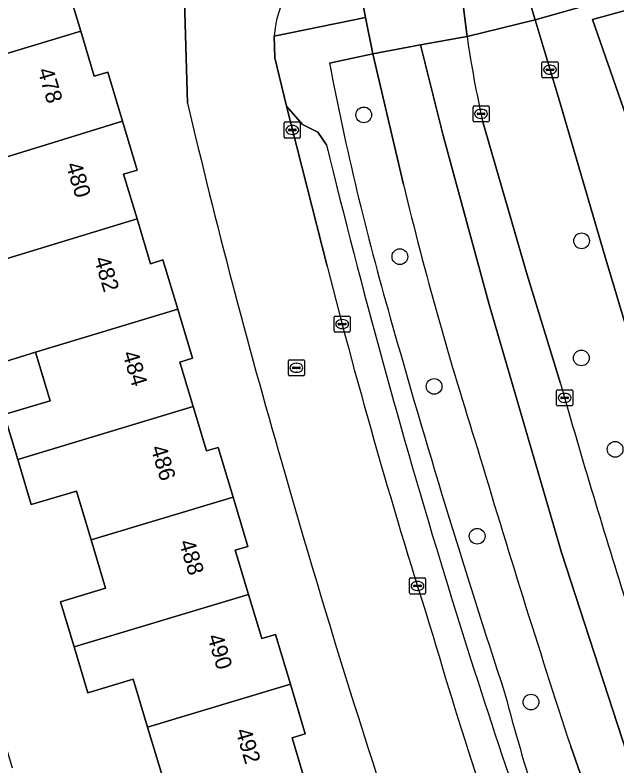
# Model space of a CAD drawing. Extents: x 157767 to 159172, y 387839 to 389425.
# Drawn here: x 158451.48 to 158488.94, y 388405.41 to 388452.12 of the extents above; entities that cross this region are included whole.
import ezdxf

# ---------------------------------------------------------------- set-up
doc = ezdxf.new("R2010")
doc.units = 0
for name, color, linetype in [('IMGEO_Berm_groen', 7, 'Continuous'), ('IMGEO_Boom', 7, 'Continuous'), ('IMGEO_Erf', 7, 'Continuous'), ('IMGEO_Kolk', 7, 'Continuous'), ('IMGEO_Pand', 7, 'Continuous'), ('IMGEO_Pand_nummerreeks', 7, 'Continuous'), ('IMGEO_Parkeervlak_open', 7, 'Continuous'), ('IMGEO_Rijbaan_lokaal_gesloten', 7, 'Continuous'), ('IMGEO_Rijbaan_lokaal_open', 7, 'Continuous'), ('IMGEO_Rioolput', 7, 'Continuous'), ('IMGEO_Verkeerseiland_open', 7, 'Continuous'), ('IMGEO_Voetpad_open', 7, 'Continuous')]:
    doc.layers.add(name, color=color, linetype=linetype)

msp = doc.modelspace()

# ---------------------------------------------------------------- linework, layer by layer
at = {"layer": 'IMGEO_Berm_groen'}
for points in [[(158490.865, 388428.213), (158488.179, 388437.145), (158485.337, 388446.848), (158483.846, 388451.832), (158479.618, 388450.796)], [(158475.648, 388441.591), (158473.746, 388449.709), (158471.053, 388449.136)], [(158480.585, 388445.534), (158483.359, 388435.96), (158485.431, 388429.209)], [(158486.242, 388396.474), (158490.11, 388386.526), (158492.771, 388387.635), (158492.15, 388389.247), (158486.063, 388406.631)]]:
    msp.add_lwpolyline(points, dxfattribs=at)
for centre, radius, start, end in [((158541.405, 388459.431), 62.388, 187.95561, 192.87057), ((158644.262, 388482.145), 176.326, 190.7896, 196.08308), ((158711.3, 388498.942), 242.53, 193.67831, 197.70967), ((159003.836, 388581.934), 549.484, 195.69418, 198.24389), ((158948.437, 388560.582), 481.283, 195.84072, 197.57658), ((159143.333, 388622.48), 691.805, 196.571755, 198.180292), ((158614.02, 388444.466), 136.494, 194.66486, 200.58574)]:
    msp.add_arc(centre, radius, start, end, dxfattribs=at)
at = {"layer": 'IMGEO_Boom'}
for centre in [(158473.184, 388445.913), (158486.742, 388438.079), (158475.434, 388437.093), (158486.726, 388430.793), (158477.565, 388429.023), (158488.828, 388425.109), (158480.242, 388419.704), (158483.595, 388409.388)]:
    msp.add_circle(centre, 0.489, dxfattribs=at)
at = {"layer": 'IMGEO_Erf'}
for points in [[(158462.219, 388446.634), (158461.817, 388460.067), (158461.803, 388460.531), (158434.092, 388452.282), (158434.544, 388450.562), (158437.436, 388451.432), (158439.023, 388446.154), (158440.77, 388440.344), (158442.52, 388434.523), (158444.276, 388428.684), (158446.04, 388422.816), (158447.8, 388416.963), (158449.546, 388411.158), (158451.307, 388405.301)], [(158454.733, 388453.91), (158455.574, 388451.115), (158456.414, 388448.321), (158457.247, 388448.571), (158458.163, 388445.526), (158459.079, 388442.478), (158458.238, 388442.225), (158459.075, 388439.443), (158459.912, 388436.658), (158460.683, 388436.89), (158461.604, 388433.826), (158462.521, 388430.777), (158461.73, 388430.539), (158462.562, 388427.772), (158463.392, 388425.011), (158464.123, 388425.23), (158465.051, 388422.144), (158465.976, 388419.066), (158465.184, 388418.828), (158466.01, 388416.082), (158466.835, 388413.338), (158467.686, 388413.593), (158468.616, 388410.499), (158469.547, 388407.404), (158468.726, 388407.157), (158469.562, 388404.375)], [(158460.631, 388404.824), (158459.726, 388407.834), (158458.832, 388410.807), (158456.011, 388409.959), (158455.152, 388412.818), (158454.306, 388415.631), (158457.114, 388416.476), (158456.211, 388419.477), (158455.298, 388422.514), (158452.493, 388421.671), (158451.652, 388424.467), (158450.808, 388427.275), (158453.668, 388428.135), (158452.763, 388431.146), (158449.935, 388430.289)]]:
    msp.add_lwpolyline(points, dxfattribs=at)
for centre, radius, start, end in [((158897.479, 388548.97), 447.128, 193.23077, 196.1824), ((158987.407, 388571.626), 539.818, 195.83174, 199.15454)]:
    msp.add_arc(centre, radius, start, end, dxfattribs=at)
at = {"layer": 'IMGEO_Kolk'}
for p, q in [((158484.275, 388448.296), (158484.275, 388449.148)), ((158484.35, 388449.222), (158485.202, 388449.222)), ((158484.763, 388449.002), (158484.788, 388449.002)), ((158485.276, 388449.148), (158485.276, 388448.296)), ((158484.534, 388448.716), (158484.534, 388448.728)), ((158484.972, 388448.679), (158484.574, 388448.679)), ((158484.577, 388448.765), (158484.975, 388448.765)), ((158484.786, 388448.442), (158484.761, 388448.442)), ((158485.018, 388448.728), (158485.018, 388448.716)), ((158485.202, 388448.222), (158484.35, 388448.222)), ((158479.985, 388445.551), (158479.985, 388446.403)), ((158480.06, 388446.477), (158480.912, 388446.477)), ((158480.473, 388446.257), (158480.498, 388446.257)), ((158480.986, 388446.403), (158480.986, 388445.551)), ((158480.244, 388445.971), (158480.244, 388445.983)), ((158480.682, 388445.934), (158480.284, 388445.934)), ((158480.287, 388446.02), (158480.685, 388446.02)), ((158480.496, 388445.697), (158480.471, 388445.697)), ((158480.728, 388445.983), (158480.728, 388445.971)), ((158468.236, 388444.547), (158468.236, 388445.399)), ((158468.311, 388445.473), (158469.163, 388445.473)), ((158468.724, 388445.253), (158468.749, 388445.253)), ((158469.237, 388445.399), (158469.237, 388444.547)), ((158480.912, 388445.477), (158480.06, 388445.477)), ((158468.495, 388444.967), (158468.495, 388444.979)), ((158468.933, 388444.93), (158468.535, 388444.93)), ((158468.538, 388445.016), (158468.936, 388445.016)), ((158468.747, 388444.693), (158468.722, 388444.693)), ((158468.979, 388444.979), (158468.979, 388444.967)), ((158469.163, 388444.473), (158468.311, 388444.473)), ((158471.338, 388432.474), (158471.338, 388433.326)), ((158471.413, 388433.4), (158472.265, 388433.4)), ((158471.826, 388433.18), (158471.851, 388433.18)), ((158472.339, 388433.326), (158472.339, 388432.474)), ((158471.597, 388432.894), (158471.597, 388432.906)), ((158472.035, 388432.857), (158471.637, 388432.857)), ((158471.64, 388432.943), (158472.038, 388432.943)), ((158471.849, 388432.62), (158471.824, 388432.62)), ((158472.081, 388432.906), (158472.081, 388432.894)), ((158472.265, 388432.4), (158471.413, 388432.4)), ((158485.261, 388428.812), (158486.113, 388428.812)), ((158485.186, 388427.886), (158485.186, 388428.738)), ((158485.445, 388428.306), (158485.445, 388428.318)), ((158485.488, 388428.355), (158485.886, 388428.355)), ((158485.674, 388428.592), (158485.699, 388428.592)), ((158485.929, 388428.318), (158485.929, 388428.306)), ((158486.187, 388428.738), (158486.187, 388427.886)), ((158485.883, 388428.269), (158485.485, 388428.269)), ((158485.697, 388428.032), (158485.672, 388428.032)), ((158486.113, 388427.812), (158485.261, 388427.812)), ((158476.101, 388417.11), (158476.953, 388417.11)), ((158476.026, 388416.184), (158476.026, 388417.036)), ((158476.328, 388416.653), (158476.726, 388416.653)), ((158476.514, 388416.89), (158476.539, 388416.89)), ((158477.027, 388417.036), (158477.027, 388416.184)), ((158476.285, 388416.604), (158476.285, 388416.616)), ((158476.723, 388416.567), (158476.325, 388416.567)), ((158476.537, 388416.33), (158476.512, 388416.33)), ((158476.769, 388416.616), (158476.769, 388416.604)), ((158476.953, 388416.11), (158476.101, 388416.11))]:
    msp.add_line(p, q, dxfattribs=at)
for points in [[(158484.275, 388448.296), (158484.275, 388449.148)], [(158484.35, 388449.222), (158485.202, 388449.222)], [(158485.276, 388449.148), (158485.276, 388448.296)], [(158485.202, 388448.222), (158484.35, 388448.222)], [(158479.985, 388445.551), (158479.985, 388446.403)], [(158480.06, 388446.477), (158480.912, 388446.477)], [(158480.986, 388446.403), (158480.986, 388445.551)], [(158468.236, 388444.547), (158468.236, 388445.399)], [(158468.311, 388445.473), (158469.163, 388445.473)], [(158469.237, 388445.399), (158469.237, 388444.547)], [(158480.912, 388445.477), (158480.06, 388445.477)], [(158469.163, 388444.473), (158468.311, 388444.473)], [(158471.338, 388432.474), (158471.338, 388433.326)], [(158471.413, 388433.4), (158472.265, 388433.4)], [(158472.339, 388433.326), (158472.339, 388432.474)], [(158472.265, 388432.4), (158471.413, 388432.4)], [(158485.261, 388428.812), (158486.113, 388428.812)], [(158485.186, 388427.886), (158485.186, 388428.738)], [(158486.187, 388428.738), (158486.187, 388427.886)], [(158486.113, 388427.812), (158485.261, 388427.812)], [(158476.101, 388417.11), (158476.953, 388417.11)], [(158476.026, 388416.184), (158476.026, 388417.036)], [(158477.027, 388417.036), (158477.027, 388416.184)], [(158476.953, 388416.11), (158476.101, 388416.11)]]:
    msp.add_lwpolyline(points, dxfattribs=at)
for centre, radius, start, end in [((158484.352, 388449.146), 0.0765, 91.552, 178.448), ((158484.352, 388449.146), 0.0765, 91.552, 178.448), ((158485.2, 388449.146), 0.0765, 1.552, 88.448), ((158485.2, 388449.146), 0.0765, 1.552, 88.448), ((158484.574, 388448.725), 0.0403, 85.8775, 175.7526), ((158484.571, 388448.715), 0.0366, 178.938, 274.7102), ((158484.975, 388448.722), 0.043, 264.8664, 352.4533), ((158484.979, 388448.727), 0.0386, 1.7309, 96.639), ((158484.352, 388448.298), 0.0765, 181.552, 268.448), ((158484.352, 388448.298), 0.0765, 181.552, 268.448), ((158485.2, 388448.298), 0.0765, 271.552, 358.448), ((158485.2, 388448.298), 0.0765, 271.552, 358.448), ((158480.062, 388446.401), 0.0765, 91.552, 178.448), ((158480.062, 388446.401), 0.0765, 91.552, 178.448), ((158480.91, 388446.401), 0.0765, 1.552, 88.448), ((158480.91, 388446.401), 0.0765, 1.552, 88.448), ((158480.284, 388445.98), 0.0403, 85.8775, 175.7526), ((158480.281, 388445.97), 0.0366, 178.938, 274.7102), ((158480.685, 388445.977), 0.043, 264.8664, 352.4533), ((158480.689, 388445.982), 0.0386, 1.7309, 96.639), ((158468.313, 388445.397), 0.0765, 91.552, 178.448), ((158468.313, 388445.397), 0.0765, 91.552, 178.448), ((158469.161, 388445.397), 0.0765, 1.552, 88.448), ((158469.161, 388445.397), 0.0765, 1.552, 88.448), ((158480.062, 388445.553), 0.0765, 181.552, 268.448), ((158480.062, 388445.553), 0.0765, 181.552, 268.448), ((158480.91, 388445.553), 0.0765, 271.552, 358.448), ((158480.91, 388445.553), 0.0765, 271.552, 358.448), ((158468.535, 388444.976), 0.0403, 85.8775, 175.7526), ((158468.532, 388444.966), 0.0366, 178.938, 274.7102), ((158468.936, 388444.973), 0.043, 264.8664, 352.4533), ((158468.94, 388444.978), 0.0386, 1.7309, 96.639), ((158468.313, 388444.549), 0.0765, 181.552, 268.448), ((158468.313, 388444.549), 0.0765, 181.552, 268.448), ((158469.161, 388444.549), 0.0765, 271.552, 358.448), ((158469.161, 388444.549), 0.0765, 271.552, 358.448), ((158471.415, 388433.324), 0.0765, 91.552, 178.448), ((158471.415, 388433.324), 0.0765, 91.552, 178.448), ((158472.263, 388433.324), 0.0765, 1.552, 88.448), ((158472.263, 388433.324), 0.0765, 1.552, 88.448), ((158471.637, 388432.903), 0.0403, 85.8775, 175.7526), ((158471.634, 388432.893), 0.0366, 178.938, 274.7102), ((158472.038, 388432.9), 0.043, 264.8664, 352.4533), ((158472.042, 388432.905), 0.0386, 1.7309, 96.639), ((158471.415, 388432.476), 0.0765, 181.552, 268.448), ((158471.415, 388432.476), 0.0765, 181.552, 268.448), ((158472.263, 388432.476), 0.0765, 271.552, 358.448), ((158472.263, 388432.476), 0.0765, 271.552, 358.448), ((158485.263, 388428.736), 0.0765, 91.552, 178.448), ((158485.263, 388428.736), 0.0765, 91.552, 178.448), ((158486.111, 388428.736), 0.0765, 1.552, 88.448), ((158486.111, 388428.736), 0.0765, 1.552, 88.448), ((158485.485, 388428.315), 0.0403, 85.8775, 175.7526), ((158485.482, 388428.305), 0.0366, 178.938, 274.7102), ((158485.886, 388428.312), 0.043, 264.8664, 352.4533), ((158485.89, 388428.317), 0.0386, 1.7309, 96.639), ((158485.263, 388427.888), 0.0765, 181.552, 268.448), ((158485.263, 388427.888), 0.0765, 181.552, 268.448), ((158486.111, 388427.888), 0.0765, 271.552, 358.448), ((158486.111, 388427.888), 0.0765, 271.552, 358.448), ((158476.103, 388417.034), 0.0765, 91.552, 178.448), ((158476.103, 388417.034), 0.0765, 91.552, 178.448), ((158476.951, 388417.034), 0.0765, 1.552, 88.448), ((158476.951, 388417.034), 0.0765, 1.552, 88.448), ((158476.325, 388416.613), 0.0403, 85.8775, 175.7526), ((158476.73, 388416.615), 0.0386, 1.7309, 96.639), ((158476.103, 388416.186), 0.0765, 181.552, 268.448), ((158476.103, 388416.186), 0.0765, 181.552, 268.448), ((158476.322, 388416.603), 0.0366, 178.938, 274.7102), ((158476.726, 388416.61), 0.043, 264.8664, 352.4533), ((158476.951, 388416.186), 0.0765, 271.552, 358.448), ((158476.951, 388416.186), 0.0765, 271.552, 358.448)]:
    msp.add_arc(centre, radius, start, end, dxfattribs=at)
for centre, major_axis, ratio, start_param, end_param in [((158484.762, 388448.722), (-0.387, 0.002), 0.722429, 4.712389, 7.853982), ((158484.787, 388448.722), (-0.39, 0.002), 0.717154, 1.570796, 4.712389), ((158480.472, 388445.977), (-0.387, 0.002), 0.722429, 4.712389, 7.853982), ((158480.497, 388445.977), (-0.39, 0.002), 0.717154, 1.570796, 4.712389), ((158468.723, 388444.973), (-0.387, 0.002), 0.722429, 4.712389, 7.853982), ((158468.748, 388444.973), (-0.39, 0.002), 0.717154, 1.570796, 4.712389), ((158471.825, 388432.9), (-0.387, 0.002), 0.722429, 4.712389, 7.853982), ((158471.85, 388432.9), (-0.39, 0.002), 0.717154, 1.570796, 4.712389), ((158485.673, 388428.312), (-0.387, 0.002), 0.722429, 4.712389, 7.853982), ((158485.698, 388428.312), (-0.39, 0.002), 0.717154, 1.570796, 4.712389), ((158476.513, 388416.61), (-0.387, 0.002), 0.722429, 4.712389, 7.853982), ((158476.538, 388416.61), (-0.39, 0.002), 0.717154, 1.570796, 4.712389)]:
    msp.add_ellipse(centre, major_axis=major_axis, ratio=ratio, start_param=start_param, end_param=end_param, dxfattribs=at)
at = {"layer": 'IMGEO_Pand'}
for points in [[(158444.709, 388447.842), (158455.574, 388451.115), (158454.733, 388453.91), (158455.527, 388454.149), (158454.564, 388457.354), (158445.669, 388454.68), (158446.645, 388451.436), (158443.878, 388450.604)], [(158458.163, 388445.526), (158457.247, 388448.571), (158456.414, 388448.321), (158455.574, 388451.115), (158444.709, 388447.842), (158445.318, 388445.816), (158445.538, 388445.084), (158448.408, 388445.946), (158449.349, 388442.815)], [(158448.182, 388436.123), (158459.075, 388439.443), (158458.238, 388442.225), (158459.079, 388442.478), (158458.163, 388445.526), (158449.349, 388442.815), (158450.252, 388439.812), (158447.336, 388438.936)], [(158460.683, 388436.89), (158459.912, 388436.658), (158459.075, 388439.443), (158448.182, 388436.123), (158449.009, 388433.371), (158449.935, 388430.289), (158452.763, 388431.146), (158461.604, 388433.826)], [(158452.763, 388431.146), (158453.668, 388428.135), (158450.808, 388427.275), (158451.652, 388424.467), (158462.562, 388427.772), (158461.73, 388430.539), (158462.521, 388430.777), (158461.604, 388433.826)], [(158451.652, 388424.467), (158452.493, 388421.671), (158455.298, 388422.514), (158456.211, 388419.477), (158465.051, 388422.144), (158464.123, 388425.23), (158463.392, 388425.011), (158462.562, 388427.772)], [(158456.211, 388419.477), (158457.114, 388416.476), (158454.306, 388415.631), (158455.152, 388412.818), (158466.01, 388416.082), (158465.184, 388418.828), (158465.976, 388419.066), (158465.051, 388422.144)], [(158459.726, 388407.834), (158468.616, 388410.499), (158467.686, 388413.593), (158466.835, 388413.338), (158466.01, 388416.082), (158455.152, 388412.818), (158456.011, 388409.959), (158458.832, 388410.807)], [(158458.705, 388401.187), (158469.562, 388404.375), (158468.726, 388407.157), (158469.547, 388407.404), (158468.616, 388410.499), (158459.726, 388407.834), (158460.631, 388404.824), (158457.862, 388403.992)]]:
    msp.add_lwpolyline(points, close=True, dxfattribs=at)
at = {"layer": 'IMGEO_Parkeervlak_open'}
msp.add_lwpolyline([(158470.873, 388444.043), (158470.335, 388444.835), (158469.374, 388445.314), (158468.375, 388446.45), (158470.903, 388436.495)], dxfattribs=at)
for centre, radius, start, end in [((158937.227, 388557.582), 479.976, 193.6831, 196.99247), ((158862.528, 388536.493), 404.191, 194.32393, 197.70862), ((158932.978, 388556.353), 475.554, 197.00049, 199.66985), ((158690.436, 388474.817), 221.585, 196.05166, 201.68659)]:
    msp.add_arc(centre, radius, start, end, dxfattribs=at)
at = {"layer": 'IMGEO_Rijbaan_lokaal_gesloten'}
for points in [[(158482.979, 388454.731), (158483.173, 388454.084), (158483.846, 388451.832), (158489.67, 388453.482), (158483.509, 388473.88), (158481.169, 388473.225), (158480.215, 388476.493), (158464.894, 388527.789), (158457.626, 388552.124)], [(158460.347, 388500.871), (158467.817, 388474.585), (158468.769, 388471.054), (158469.254, 388469.283), (158469.644, 388467.803), (158470.103, 388466.062), (158470.659, 388463.951), (158472.429, 388456.547), (158473.283, 388451.967), (158473.746, 388449.709), (158476.721, 388450.26), (158479.618, 388450.796), (158479.434, 388452.243), (158479.326, 388453.166), (158474.917, 388467.343), (158474.572, 388467.963), (158474.07, 388469.047), (158472.916, 388471.756), (158472.242, 388473.65), (158471.618, 388475.618), (158471.29, 388476.65), (158471.173, 388477.014), (158469.558, 388482.246), (158464.469, 388499.312)], [(158496.729, 388424.736), (158496.69, 388424.893), (158491.444, 388440.295), (158487.411, 388451.839), (158489.906, 388452.522), (158489.67, 388453.482), (158483.846, 388451.832), (158485.337, 388446.848), (158488.179, 388437.145), (158490.865, 388428.213), (158493.302, 388420.041), (158495.403, 388412.918), (158497.881, 388404.936), (158500, 388398.432), (158502.255, 388391.492), (158507.198, 388393.62), (158504.866, 388399.935)], [(158479.618, 388450.796), (158476.721, 388450.26), (158478.122, 388444.635), (158480.989, 388434.11), (158485.493, 388418.685), (158490.425, 388403.535), (158492.167, 388398.623), (158495.643, 388388.818), (158498.301, 388389.912), (158494.751, 388399.999)], [(158476.721, 388450.26), (158473.746, 388449.709), (158475.648, 388441.591)], [(158486.063, 388406.631), (158492.15, 388389.247), (158492.771, 388387.635), (158495.643, 388388.818), (158492.167, 388398.623), (158490.425, 388403.535), (158485.493, 388418.685), (158480.989, 388434.11), (158478.122, 388444.635), (158476.721, 388450.26)], [(158485.431, 388429.209), (158483.359, 388435.96), (158480.585, 388445.534)]]:
    msp.add_lwpolyline(points, dxfattribs=at)
msp.add_lwpolyline([(158489.906, 388452.522), (158487.411, 388451.839), (158491.444, 388440.295), (158496.69, 388424.893)], close=True, dxfattribs=at)
for centre, radius, start, end in [((158541.405, 388459.431), 62.388, 187.95561, 192.87057), ((158711.3, 388498.942), 242.53, 193.67831, 197.70967), ((158948.437, 388560.582), 481.283, 195.84072, 197.57658), ((159143.333, 388622.48), 691.805, 196.571755, 198.180292)]:
    msp.add_arc(centre, radius, start, end, dxfattribs=at)
at = {"layer": 'IMGEO_Rijbaan_lokaal_open'}
for points in [[(158469.112, 388461.978), (158467.329, 388461.511), (158461.817, 388460.067), (158462.219, 388446.634)], [(158470.903, 388436.495), (158468.375, 388446.45), (158467.655, 388449.466), (158467.605, 388450.808)]]:
    msp.add_lwpolyline(points, dxfattribs=at)
for centre, radius, start, end in [((158473.946, 388450.375), 6.355, 103.8062, 176.0953), ((158897.479, 388548.97), 447.128, 193.23077, 196.1824), ((158862.528, 388536.493), 404.191, 194.32393, 197.70862), ((158987.407, 388571.626), 539.818, 195.83174, 199.15454), ((158690.436, 388474.817), 221.585, 196.05166, 201.68659)]:
    msp.add_arc(centre, radius, start, end, dxfattribs=at)
at = {"layer": 'IMGEO_Rioolput'}
for p, q in [((158468.568, 388430.68), (158469.42, 388430.68)), ((158468.493, 388429.754), (158468.493, 388430.606)), ((158468.752, 388430.174), (158468.752, 388430.186)), ((158468.795, 388430.223), (158469.193, 388430.223)), ((158468.981, 388430.46), (158469.006, 388430.46)), ((158469.236, 388430.186), (158469.236, 388430.174)), ((158469.494, 388430.606), (158469.494, 388429.754)), ((158469.19, 388430.137), (158468.792, 388430.137)), ((158469.004, 388429.9), (158468.979, 388429.9)), ((158469.42, 388429.68), (158468.568, 388429.68))]:
    msp.add_line(p, q, dxfattribs=at)
for points in [[(158468.568, 388430.68), (158469.42, 388430.68)], [(158468.493, 388429.754), (158468.493, 388430.606)], [(158469.494, 388430.606), (158469.494, 388429.754)], [(158469.42, 388429.68), (158468.568, 388429.68)]]:
    msp.add_lwpolyline(points, dxfattribs=at)
for centre, radius, start, end in [((158468.57, 388430.604), 0.0765, 91.552, 178.448), ((158468.57, 388430.604), 0.0765, 91.552, 178.448), ((158469.418, 388430.604), 0.0765, 1.552, 88.448), ((158469.418, 388430.604), 0.0765, 1.552, 88.448), ((158468.792, 388430.183), 0.0403, 85.8775, 175.7526), ((158468.789, 388430.173), 0.0366, 178.938, 274.7102), ((158469.193, 388430.18), 0.043, 264.8664, 352.4533), ((158469.197, 388430.185), 0.0386, 1.7309, 96.639), ((158468.57, 388429.756), 0.0765, 181.552, 268.448), ((158468.57, 388429.756), 0.0765, 181.552, 268.448), ((158469.418, 388429.756), 0.0765, 271.552, 358.448), ((158469.418, 388429.756), 0.0765, 271.552, 358.448)]:
    msp.add_arc(centre, radius, start, end, dxfattribs=at)
for centre, major_axis, ratio, start_param, end_param in [((158468.98, 388430.18), (-0.387, 0.002), 0.722429, 4.712389, 7.853982), ((158469.005, 388430.18), (-0.39, 0.002), 0.717154, 1.570796, 4.712389)]:
    msp.add_ellipse(centre, major_axis=major_axis, ratio=ratio, start_param=start_param, end_param=end_param, dxfattribs=at)
at = {"layer": 'IMGEO_Verkeerseiland_open'}
msp.add_lwpolyline([(158467.605, 388450.808), (158473.283, 388451.967), (158472.429, 388456.547)], dxfattribs=at)
msp.add_arc((158473.946, 388450.375), 6.355, 103.8062, 176.0953, dxfattribs=at)
at = {"layer": 'IMGEO_Voetpad_open'}
msp.add_lwpolyline([(158483.846, 388451.832), (158483.173, 388454.084), (158479.326, 388453.166), (158479.434, 388452.243), (158479.618, 388450.796)], close=True, dxfattribs=at)
msp.add_lwpolyline([(158471.053, 388449.136), (158473.746, 388449.709), (158473.283, 388451.967), (158467.605, 388450.808), (158467.655, 388449.466), (158468.375, 388446.45), (158469.374, 388445.314), (158470.335, 388444.835), (158470.873, 388444.043)], dxfattribs=at)
for centre, radius, start, end in [((158644.262, 388482.145), 176.326, 190.7896, 196.08308), ((158937.227, 388557.582), 479.976, 193.6831, 196.99247), ((159003.836, 388581.934), 549.484, 195.69418, 198.24389), ((158932.978, 388556.353), 475.554, 197.00049, 199.66985), ((158614.02, 388444.466), 136.494, 194.66486, 200.58574)]:
    msp.add_arc(centre, radius, start, end, dxfattribs=at)

# ---------------------------------------------------------------- texts
at = {"layer": 'IMGEO_Pand_nummerreeks'}
for s, rotation, p in [('478', 286.6909, (158452.872, 388448.685)), ('480', 286.6909, (158454.633, 388442.814)), ('482', 286.6901, (158456.391, 388436.95)), ('484', 286.6909, (158458.152, 388431.076)), ('486', 286.6909, (158459.912, 388425.206)), ('488', 286.6909, (158461.673, 388419.333)), ('490', 286.6909, (158463.434, 388413.462)), ('492', 286.6909, (158465.192, 388407.598))]:
    msp.add_text(s, height=1, rotation=rotation, dxfattribs=at).set_placement(p)

doc.saveas('drawing.dxf')
